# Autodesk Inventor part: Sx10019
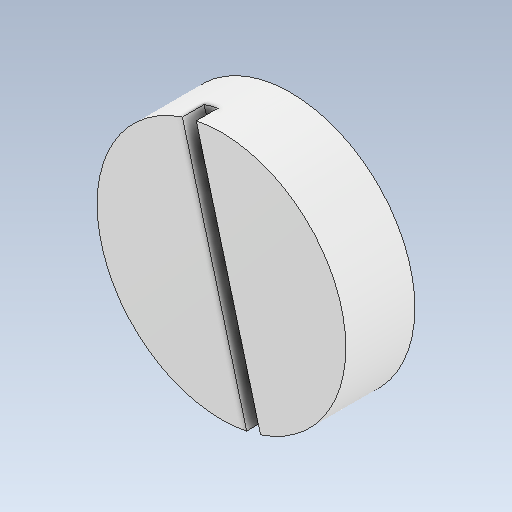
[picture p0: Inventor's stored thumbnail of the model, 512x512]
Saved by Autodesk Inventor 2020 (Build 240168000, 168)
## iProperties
Created: 2021-02
Part Number: Sx10019
Material: Generico
Document SubType Name: Modeling
Designer: zambolin
Density: 1 g/cm^3
Appearance: Default
Author: zambolin
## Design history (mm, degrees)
feature "Solido2"
node "Solido1"
